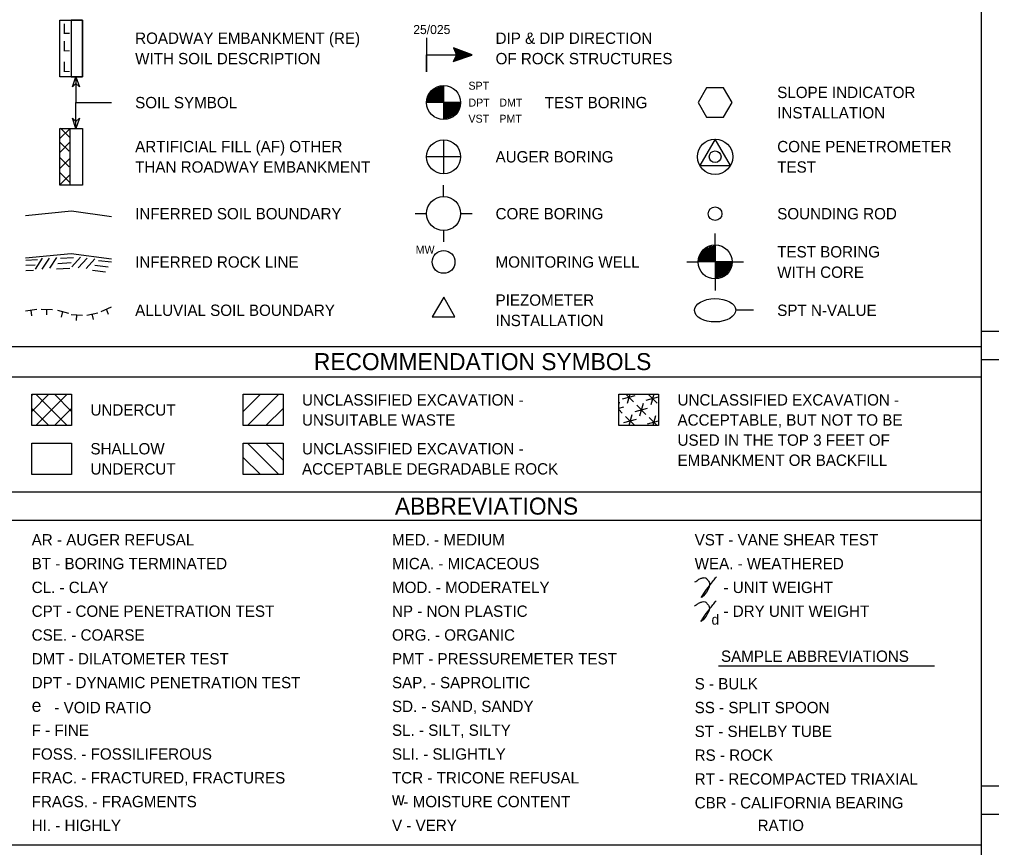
# Model space of a CAD drawing. Extents: x 265553 to 275568, y 168312 to 173522.
# Drawn here: x 267302.4 to 267674.3, y 170418.4 to 170735.3 of the extents above; entities that cross this region are included whole.
import ezdxf

# ---------------------------------------------------------------- set-up
doc = ezdxf.new("R2010")
doc.units = 0
doc.layers.add('Geotech Sheets and Borders Cell', color=7, linetype='Continuous')

msp = doc.modelspace()

# ---------------------------------------------------------------- linework, layer by layer
at = {"layer": 'Geotech Sheets and Borders Cell'}
for p, q in [((267670.42, 171052.08), (267670.42, 170249.94)), ((267322.23, 170735.1), (267322.23, 170713.41)), ((267464.72, 170710.03), (267464.72, 170697.01)), ((267471.23, 170703.52), (267458.21, 170703.52)), ((267317.94, 170689.77), (267321.67, 170693.5)), ((267321.67, 170690.16), (267318.15, 170693.68)), ((267321.75, 170693.37), (267321.75, 170671.86)), ((267317.85, 170684.48), (267321.75, 170688.39)), ((267321.49, 170684.87), (267317.94, 170688.43)), ((267464.72, 170689.29), (267464.72, 170676.28)), ((267317.94, 170678.36), (267321.75, 170682.18)), ((267321.49, 170678.93), (267318.02, 170682.4)), ((267471.23, 170682.78), (267458.21, 170682.78)), ((267321.71, 170672.99), (267318.02, 170676.67)), ((267317.98, 170672.2), (267321.8, 170676.02)), ((267464.72, 170667.54), (267464.72, 170671.88)), ((267453.87, 170661.03), (267458.21, 170661.03)), ((267471.23, 170661.03), (267475.57, 170661.03)), ((267464.72, 170654.53), (267464.72, 170650.19)), ((267568.58, 170649.03), (267568.58, 170653.37)), ((267568.58, 170649.03), (267568.58, 170636.01)), ((267304.93, 170643.17), (267309.31, 170643.48)), ((267308.57, 170639.79), (267311.31, 170643.95)), ((267311.18, 170639.83), (267313.87, 170644)), ((267314.04, 170640.14), (267316.73, 170644.3)), ((267318.2, 170643.95), (267323.15, 170644.26)), ((267322.45, 170640.7), (267325.84, 170644.34)), ((267324.93, 170640.27), (267328.35, 170643.95)), ((267327.92, 170640.05), (267331.22, 170643.69)), ((267332.65, 170643.09), (267337.59, 170642.52)), ((267304.93, 170641.26), (267308.4, 170641.48)), ((267304.93, 170639.23), (267307.79, 170639.4)), ((267316.64, 170639.88), (267321.67, 170640.18)), ((267317.16, 170641.92), (267322.24, 170642.26)), ((267330.39, 170639.4), (267335.38, 170638.75)), ((267331.22, 170641.26), (267336.34, 170640.7)), ((267557.74, 170642.52), (267562.08, 170642.52)), ((267575.09, 170642.52), (267562.08, 170642.52)), ((267575.09, 170642.52), (267579.43, 170642.52)), ((267568.58, 170636.01), (267568.58, 170631.67)), ((267304.75, 170623.82), (267309.05, 170624.43)), ((267307.22, 170621.96), (267306.92, 170624.13)), ((267310.74, 170624.47), (267315.08, 170624.34)), ((267312.86, 170622.26), (267312.91, 170624.39)), ((267333.69, 170623.56), (267337.68, 170625.3)), ((267336.55, 170622.43), (267335.68, 170624.43)), ((267576.46, 170624.15), (267583.32, 170624.15)), ((267316.94, 170624.04), (267321.15, 170622.95)), ((267318.5, 170621.39), (267319.07, 170623.52)), ((267322.23, 170622.43), (267326.57, 170622.22)), ((267324.32, 170620.18), (267324.4, 170622.3)), ((267328.18, 170622.17), (267332.43, 170623.08)), ((267330.74, 170620.53), (267330.3, 170622.65)), ((267670.42, 170616.07), (268066.96, 170616.07)), ((266920.42, 170610.2), (267670.42, 170610.2)), ((267670.42, 170605.22), (268066.96, 170605.22)), ((266920.42, 170598.59), (267670.42, 170598.59)), ((267307.48, 170591.92), (267307.11, 170591.55)), ((267313.67, 170591.92), (267307.11, 170585.36)), ((267320.75, 170591.92), (267308.71, 170579.89)), ((267308.71, 170591.92), (267320.75, 170579.89)), ((267315.78, 170591.92), (267322.35, 170585.36)), ((267388.04, 170585.36), (267394.61, 170591.92)), ((267389.64, 170579.89), (267401.68, 170591.92)), ((267533.17, 170590.1), (267538, 170591.39)), ((267534.41, 170591.92), (267537.35, 170588.98)), ((267535.9, 170591.92), (267534.93, 170588.33)), ((267542.24, 170589.63), (267546.95, 170590.89)), ((267543.01, 170591.92), (267546.42, 170588.5)), ((267545.1, 170591.92), (267544.01, 170587.86)), ((267531.93, 170588.86), (267531.71, 170588.05)), ((267531.71, 170586.56), (267533.7, 170587.09)), ((267538.59, 170587.74), (267542.12, 170584.21)), ((267541, 170588.39), (267539.71, 170583.56)), ((267307.11, 170586.45), (267313.67, 170579.89)), ((267322.35, 170586.45), (267315.78, 170579.89)), ((267396.72, 170579.89), (267403.28, 170586.45)), ((267531.71, 170586.02), (267533.05, 170584.68)), ((267534.29, 170583.44), (267537.82, 170579.91)), ((267536.7, 170584.09), (267535.58, 170579.89)), ((267537.94, 170585.33), (267542.77, 170586.62)), ((267545.77, 170583.62), (267544.78, 170579.89)), ((267533.64, 170581.03), (267538.47, 170582.32)), ((267542.71, 170580.55), (267546.95, 170581.69)), ((267543.36, 170582.97), (267546.44, 170579.89)), ((267401.68, 170561.18), (267389.64, 170573.22)), ((267403.28, 170566.65), (267396.72, 170573.22)), ((267394.61, 170561.18), (267388.04, 170567.75)), ((267297.82, 170554.51), (267670.42, 170554.51)), ((267297.82, 170543.66), (267670.42, 170543.66)), ((267569.89, 170487.91), (267652.55, 170487.91)), ((268420.42, 170441.94), (267670.42, 170441.94)), ((268066.96, 170431.1), (267670.42, 170431.1)), ((267297.82, 170419.46), (267670.42, 170419.46))]:
    msp.add_line(p, q, dxfattribs=at)
for points in [[(267317.89, 170735.1), (267326.57, 170735.1), (267326.57, 170713.41), (267317.89, 170713.41)], [(267322.23, 170713.41), (267326.57, 170713.41), (267326.57, 170735.1), (267322.23, 170735.1)], [(267322.75, 170709.51), (267324.05, 170713.41), (267325.35, 170709.51), (267324.05, 170710.81)], [(267325.35, 170697.53), (267324.05, 170693.63), (267322.75, 170697.53), (267324.05, 170696.23)], [(267317.89, 170693.63), (267326.57, 170693.63), (267326.57, 170671.94), (267317.89, 170671.94)], [(267568.58, 170689.53), (267562.74, 170679.41), (267574.43, 170679.41)], [(267307.11, 170591.92), (267322.35, 170591.92), (267322.35, 170579.89), (267307.11, 170579.89)], [(267388.04, 170591.92), (267403.28, 170591.92), (267403.28, 170579.89), (267388.04, 170579.89)], [(267531.71, 170591.92), (267546.95, 170591.92), (267546.95, 170579.89), (267531.71, 170579.89)], [(267307.11, 170573.22), (267322.35, 170573.22), (267322.35, 170561.18), (267307.11, 170561.18)], [(267307.11, 170573.22), (267322.35, 170573.22), (267322.35, 170561.18), (267307.11, 170561.18)], [(267388.04, 170573.22), (267403.28, 170573.22), (267403.28, 170561.18), (267388.04, 170561.18)]]:
    msp.add_lwpolyline(points, close=True, dxfattribs=at)
for points in [[(267458.21, 170728.26), (267458.21, 170715.25), (267458.21, 170721.76), (267475.57, 170721.76), (267468.5, 170724.49), (267469.58, 170721.76), (267468.54, 170719.5), (267468.41, 170719.24), (267475.48, 170721.71), (267469.75, 170721.63), (267468.67, 170719.41), (267474.83, 170721.54), (267471.06, 170721.54), (267469.8, 170721.5), (267468.89, 170719.63), (267474.22, 170721.45), (267469.93, 170721.45), (267469.19, 170719.85), (267473.83, 170721.45), (267469.54, 170721.28), (267470.06, 170721.19), (267469.32, 170719.94), (267470.1, 170721.45), (267473.31, 170721.28), (267469.58, 170720.07), (267470.27, 170721.24), (267472.88, 170721.24), (267469.84, 170720.33), (267470.32, 170721.15), (267472.18, 170721.15), (267470.14, 170720.5), (267470.36, 170721.11), (267471.49, 170721.11), (267470.4, 170720.72), (267470.53, 170720.98), (267471.06, 170720.93), (267470.66, 170720.85), (267469.8, 170720.46), (267470.06, 170721.02), (267469.58, 170720.11), (267469.06, 170719.85), (267469.75, 170721.28), (267469.28, 170722.97), (267468.71, 170724.23), (267475.09, 170721.84), (267469.67, 170721.93), (267474.66, 170722.02), (267468.97, 170724.06), (267469.75, 170721.84), (267473.96, 170722.06), (267469.84, 170722.06), (267469.23, 170723.84), (267469.54, 170723.62), (267469.84, 170722.19), (267469.71, 170723.62), (267474.05, 170722.1), (267469.97, 170722.19), (267469.8, 170723.36), (267473.44, 170722.28), (267470.06, 170722.32), (267472.92, 170722.32), (267469.93, 170723.23), (267472.4, 170722.32), (267469.84, 170723.06), (267470.1, 170722.49), (267471.84, 170722.28), (267470.49, 170722.58), (267469.93, 170722.54), (267470.01, 170722.8), (267471.88, 170722.45), (267470.1, 170722.89), (267469.75, 170723.58), (267471.62, 170722.84), (267469.23, 170723.8), (267469.84, 170723.1), (267469.41, 170723.54), (267469.58, 170723.23), (267469.67, 170723.02)], [(267324.05, 170713.41), (267324.05, 170703.52), (267337.68, 170703.52)], [(267458.3, 170703.73), (267464.68, 170703.81), (267458.3, 170703.86), (267458.65, 170703.9), (267464.68, 170703.99), (267458.3, 170704.07), (267464.64, 170704.2), (267458.39, 170704.25), (267464.64, 170704.38), (267458.35, 170704.51), (267464.68, 170704.59), (267458.48, 170704.72), (267464.68, 170704.85), (267458.52, 170704.98), (267464.64, 170705.11), (267458.52, 170705.24), (267464.68, 170705.29), (267458.69, 170705.5), (267464.68, 170705.5), (267458.74, 170705.72), (267464.68, 170705.72), (267458.82, 170705.98), (267464.72, 170705.94), (267459, 170706.24), (267464.68, 170706.2), (267459.13, 170706.55), (267464.72, 170706.42), (267459.39, 170706.85), (267464.72, 170706.72), (267459.52, 170707.11), (267464.68, 170706.98), (267459.78, 170707.41), (267464.68, 170707.33), (267460.04, 170707.72), (267464.68, 170707.59), (267460.3, 170708.02), (267464.77, 170707.85), (267460.69, 170708.37), (267464.68, 170708.19), (267461.12, 170708.67), (267464.68, 170708.54), (267461.69, 170708.97), (267464.68, 170708.89), (267462.42, 170709.32), (267464.64, 170709.23), (267463.33, 170709.5), (267464.68, 170709.58), (267464.03, 170709.71)], [(267565.33, 170697.88), (267571.83, 170697.88), (267575.09, 170703.52), (267571.83, 170709.16), (267565.33, 170709.16), (267562.07, 170703.52), (267565.33, 170697.88)], [(267324.05, 170693.63), (267324.05, 170703.56)], [(267471.11, 170703.35), (267464.73, 170703.26), (267471.11, 170703.22), (267470.76, 170703.17), (267464.73, 170703.09), (267471.11, 170703), (267464.77, 170702.87), (267471.02, 170702.82), (267464.77, 170702.69), (267471.06, 170702.56), (267464.73, 170702.48), (267470.93, 170702.35), (267464.73, 170702.22), (267470.89, 170702.09), (267464.77, 170701.96), (267470.89, 170701.83), (267464.73, 170701.78), (267470.72, 170701.57), (267464.73, 170701.57), (267470.67, 170701.35), (267464.73, 170701.35), (267470.59, 170701.09), (267464.69, 170701.13), (267470.41, 170700.83), (267464.73, 170700.87), (267470.28, 170700.53), (267464.69, 170700.66), (267470.02, 170700.22), (267464.69, 170700.35), (267469.89, 170699.96), (267464.73, 170700.09), (267469.63, 170699.66), (267464.73, 170699.74), (267469.37, 170699.35), (267464.73, 170699.48), (267469.11, 170699.05), (267464.64, 170699.22), (267468.72, 170698.7), (267464.73, 170698.88), (267468.29, 170698.4), (267464.73, 170698.53), (267467.72, 170698.1), (267464.73, 170698.18), (267466.99, 170697.75), (267464.77, 170697.84), (267466.07, 170697.58), (267464.73, 170697.49), (267465.38, 170697.36)], [(267304.75, 170660.37), (267322.32, 170662.04), (267337.68, 170659.96)], [(267562.16, 170642.73), (267568.54, 170642.81), (267562.16, 170642.86), (267562.51, 170642.9), (267568.54, 170642.99), (267562.16, 170643.07), (267568.5, 170643.2), (267562.25, 170643.25), (267568.5, 170643.38), (267562.21, 170643.51), (267568.54, 170643.59), (267562.34, 170643.72), (267568.54, 170643.85), (267562.38, 170643.98), (267568.5, 170644.11), (267562.38, 170644.24), (267568.54, 170644.29), (267562.55, 170644.5), (267568.54, 170644.5), (267562.6, 170644.72), (267568.54, 170644.72), (267562.68, 170644.98), (267568.58, 170644.94), (267562.86, 170645.24), (267568.54, 170645.2), (267562.99, 170645.55), (267568.58, 170645.42), (267563.25, 170645.85), (267568.58, 170645.72), (267563.38, 170646.11), (267568.54, 170645.98), (267563.64, 170646.41), (267568.54, 170646.33), (267563.9, 170646.72), (267568.54, 170646.59), (267564.16, 170647.02), (267568.63, 170646.85), (267564.55, 170647.37), (267568.54, 170647.19), (267564.98, 170647.67), (267568.54, 170647.54), (267565.55, 170647.97), (267568.54, 170647.89), (267566.28, 170648.32), (267568.5, 170648.23), (267567.19, 170648.5), (267568.54, 170648.58), (267567.89, 170648.71)], [(267304.75, 170644.15), (267322.28, 170645.82), (267337.68, 170643.73)], [(267574.97, 170642.35), (267568.59, 170642.26), (267574.97, 170642.22), (267574.62, 170642.17), (267568.59, 170642.09), (267574.97, 170642), (267568.63, 170641.87), (267574.88, 170641.82), (267568.63, 170641.69), (267574.92, 170641.56), (267568.59, 170641.48), (267574.79, 170641.35), (267568.59, 170641.22), (267574.75, 170641.09), (267568.63, 170640.96), (267574.75, 170640.83), (267568.59, 170640.78), (267574.58, 170640.57), (267568.59, 170640.57), (267574.53, 170640.35), (267568.59, 170640.35), (267574.45, 170640.09), (267568.55, 170640.13), (267574.27, 170639.83), (267568.59, 170639.87), (267574.14, 170639.53), (267568.55, 170639.66), (267573.88, 170639.22), (267568.55, 170639.35), (267573.75, 170638.96), (267568.59, 170639.09), (267573.49, 170638.66), (267568.59, 170638.74), (267573.23, 170638.35), (267568.59, 170638.48), (267572.97, 170638.05), (267568.5, 170638.22), (267572.58, 170637.7), (267568.59, 170637.88), (267572.15, 170637.4), (267568.59, 170637.53), (267571.58, 170637.1), (267568.59, 170637.18), (267570.85, 170636.75), (267568.63, 170636.84), (267569.93, 170636.58), (267568.59, 170636.49), (267569.24, 170636.36)], [(267460.39, 170621.54), (267469.06, 170621.54), (267464.73, 170629.04), (267460.39, 170621.54)]]:
    msp.add_lwpolyline(points, dxfattribs=at)
for centre, radius in [((267464.72, 170703.52), 6.51), ((267464.72, 170682.78), 6.51), ((267464.72, 170661.03), 6.51), ((267568.58, 170661), 2.6), ((267464.72, 170642.52), 4.34), ((267568.58, 170642.52), 6.51)]:
    msp.add_circle(centre, radius, dxfattribs=at)
for centre, major_axis, ratio in [((267568.58, 170682.78), (0, 6.75), 0.999997), ((267568.58, 170682.78), (0, 2.25), 0.999997), ((267568.58, 170624.04), (7.87, 0.11), 0.568627)]:
    msp.add_ellipse(centre, major_axis=major_axis, ratio=ratio, dxfattribs=at)
for points in [[(267560.8, 170520.14), (267561.54, 170520.49), (267562.68, 170521.28), (267563.81, 170521.63), (267564.94, 170521.63), (267565.68, 170520.88), (267566.42, 170519.75), (267563.42, 170514.13), (267566.42, 170518.62), (267569.07, 170522.02)], [(267560.69, 170510.98), (267561.43, 170511.33), (267562.56, 170512.1), (267563.68, 170512.46), (267564.81, 170512.46), (267565.56, 170511.72), (267566.3, 170510.59), (267563.3, 170504.97), (267566.3, 170509.45), (267568.95, 170512.84)]]:
    msp.add_spline(points, degree=3, dxfattribs=at)

# ---------------------------------------------------------------- texts
for s, height, p in [('L', 3.9, (267318.96, 170729.81)), ('25/025', 3.47, (267453.1, 170729.74)), ('ROADWAY EMBANKMENT (RE)', 4.3381, (267346.7, 170725.99)), ('DIP & DIP DIRECTION', 4.3381, (267484.59, 170725.99)), ('L', 3.9, (267318.96, 170723.13)), ('WITH SOIL DESCRIPTION', 4.3381, (267346.7, 170718.18)), ('OF ROCK STRUCTURES', 4.3381, (267484.59, 170718.18)), ('L', 3.9, (267318.96, 170715.23)), ('SPT', 3.037, (267474.22, 170708.46)), ('SLOPE INDICATOR', 4.3381, (267592.34, 170705.25)), ('SOIL SYMBOL', 4.3381, (267346.7, 170701.35)), ('DPT', 3.037, (267474.22, 170702)), ('DMT', 3.037, (267486.03, 170702)), ('TEST BORING', 4.3381, (267503.37, 170701.35)), ('VST', 3.037, (267474.22, 170695.84)), ('PMT', 3.037, (267486.03, 170695.84)), ('INSTALLATION', 4.3381, (267592.34, 170697.45)), ('ARTIFICIAL FILL (AF) OTHER', 4.3381, (267346.7, 170684.52)), ('CONE PENETROMETER', 4.3381, (267592.34, 170684.52)), ('AUGER BORING', 4.3381, (267484.59, 170680.61)), ('THAN ROADWAY EMBANKMENT', 4.3381, (267346.7, 170676.71)), ('TEST', 4.338, (267592.34, 170676.71)), ('INFERRED SOIL BOUNDARY', 4.3381, (267346.7, 170658.83)), ('CORE BORING', 4.3381, (267484.59, 170658.83)), ('SOUNDING ROD', 4.3381, (267592.34, 170658.83)), ('TEST BORING', 4.3381, (267592.34, 170644.25)), ('INFERRED ROCK LINE', 4.3381, (267346.7, 170640.35)), ('MONITORING WELL', 4.3381, (267484.59, 170640.35)), ('WITH CORE ', 4.338, (267592.34, 170636.45)), ('PIEZOMETER', 4.338, (267484.59, 170625.78)), ('ALLUVIAL SOIL BOUNDARY', 4.3381, (267346.7, 170621.87)), ('SPT N-VALUE', 4.3381, (267592.34, 170621.87)), ('INSTALLATION', 4.3381, (267484.59, 170617.97)), ('RECOMMENDATION SYMBOLS', 6.507, (267415.08, 170601.14)), ('UNCLASSIFIED EXCAVATION -', 4.3381, (267410.53, 170587.58)), ('UNCLASSIFIED EXCAVATION -', 4.3381, (267554.2, 170587.58)), ('UNDERCUT', 4.338, (267329.6, 170583.73)), ('UNSUITABLE WASTE', 4.3381, (267410.53, 170579.89)), ('ACCEPTABLE, BUT NOT TO BE', 4.3381, (267554.2, 170579.89)), ('USED IN THE TOP 3 FEET OF', 4.3381, (267554.2, 170572.19)), ('SHALLOW', 4.338, (267329.6, 170568.88)), ('UNCLASSIFIED EXCAVATION -', 4.3381, (267410.53, 170568.88)), ('EMBANKMENT OR BACKFILL', 4.3381, (267554.2, 170564.49)), ('UNDERCUT', 4.338, (267329.6, 170561.18)), ('ACCEPTABLE DEGRADABLE ROCK', 4.3381, (267410.53, 170561.18)), ('ABBREVIATIONS', 6.507, (267446.08, 170545.84)), ('AR - AUGER REFUSAL', 4.3381, (267307.11, 170534.04)), ('MED. - MEDIUM', 4.3381, (267444.96, 170534.04)), ('VST - VANE SHEAR TEST', 4.3381, (267560.75, 170534.04)), ('BT - BORING TERMINATED', 4.3381, (267307.11, 170524.94)), ('MICA. - MICACEOUS', 4.3381, (267444.96, 170524.94)), ('WEA. - WEATHERED', 4.3381, (267560.75, 170524.94)), ('CL. - CLAY', 4.338, (267307.11, 170515.83)), ('MOD. - MODERATELY', 4.3381, (267444.96, 170515.83)), ('- UNIT WEIGHT ', 4.3381, (267571.77, 170515.83)), ('CPT - CONE PENETRATION TEST', 4.3381, (267307.11, 170506.72)), ('NP - NON PLASTIC', 4.3381, (267444.96, 170506.72)), ('- DRY UNIT WEIGHT', 4.3381, (267571.77, 170506.72)), ('d', 3.9, (267567.2, 170503.72)), ('CSE. - COARSE', 4.3381, (267307.11, 170497.61)), ('ORG. - ORGANIC', 4.3381, (267444.96, 170497.61)), ('DMT - DILATOMETER TEST', 4.3381, (267307.11, 170488.5)), ('PMT - PRESSUREMETER TEST', 4.3381, (267444.96, 170488.5)), ('SAMPLE ABBREVIATIONS', 4.3381, (267570.83, 170489.49)), ('DPT - DYNAMIC PENETRATION TEST', 4.3381, (267307.11, 170479.39)), ('SAP. - SAPROLITIC', 4.3381, (267444.96, 170479.39)), ('S - BULK', 4.338, (267560.75, 170478.95)), ('e', 5, (267307.11, 170470.37)), ('- VOID RATIO', 4.3381, (267315.79, 170469.85)), ('SD. - SAND, SANDY', 4.3381, (267444.96, 170470.29)), ('SS - SPLIT SPOON', 4.3381, (267560.75, 170469.85)), ('F - FINE', 4.338, (267307.11, 170461.18)), ('SL. - SILT, SILTY', 4.3381, (267444.96, 170461.18)), ('ST - SHELBY TUBE', 4.3381, (267560.75, 170460.74)), ('FOSS. - FOSSILIFEROUS', 4.3381, (267307.11, 170452.07)), ('SLI. - SLIGHTLY', 4.3381, (267444.96, 170452.07)), ('RS - ROCK', 4.338, (267560.75, 170451.63)), ('FRAC. - FRACTURED, FRACTURES', 4.3381, (267307.11, 170442.96)), ('TCR - TRICONE REFUSAL', 4.3381, (267444.96, 170442.96)), ('RT - RECOMPACTED TRIAXIAL', 4.3381, (267560.75, 170442.52)), ('FRAGS. - FRAGMENTS', 4.3381, (267307.11, 170433.85)), ('w', 5, (267444.96, 170434.6)), ('  - MOISTURE CONTENT', 4.3381, (267446.1, 170433.85)), ('CBR - CALIFORNIA BEARING', 4.3381, (267560.75, 170433.41)), ('HI. - HIGHLY', 4.3381, (267307.11, 170424.74)), ('V - VERY', 4.338, (267444.96, 170424.74)), ('RATIO', 4.338, (267584.83, 170424.74))]:
    msp.add_text(s, height=height, dxfattribs=at).set_placement(p)
msp.add_text('MW', height=3.037, rotation=360, dxfattribs=at).set_placement((267454.03, 170645.72))

doc.saveas('drawing.dxf')
